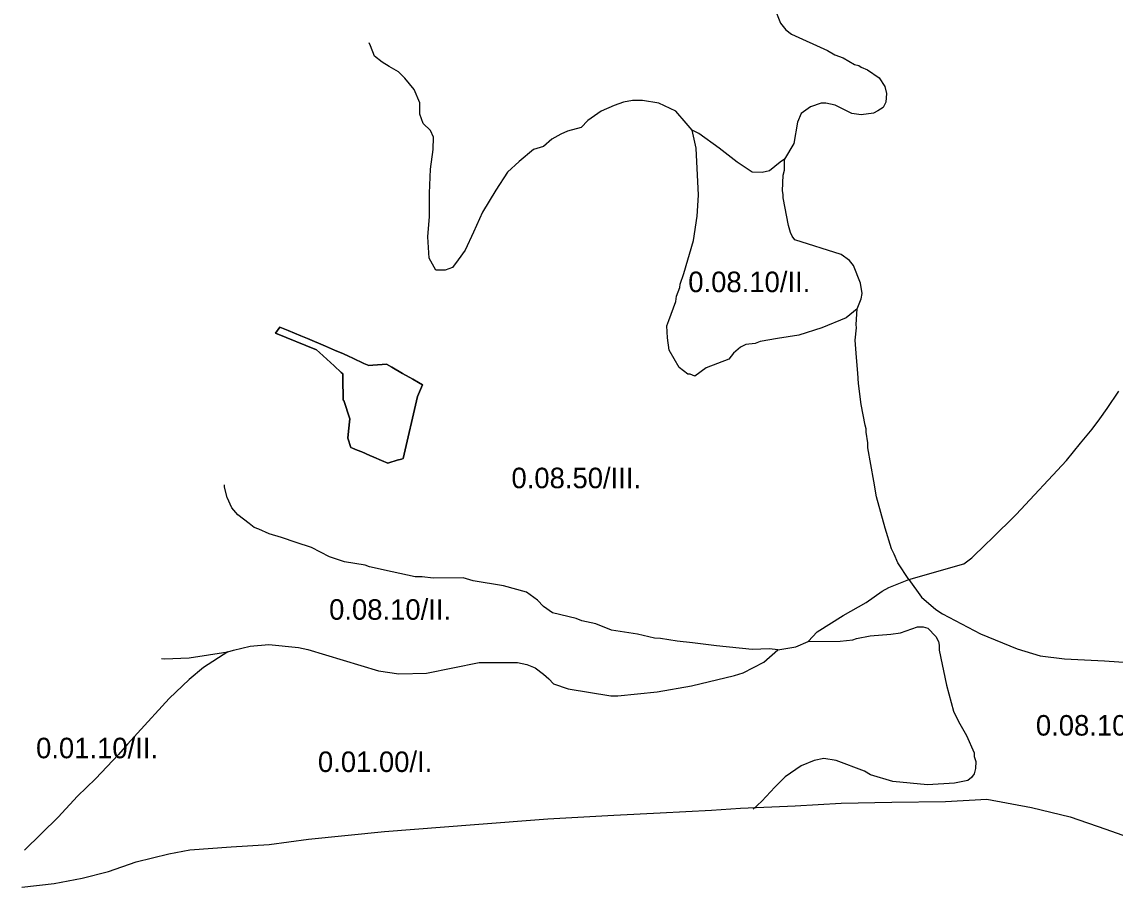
# Model space of a CAD drawing. Extents: x -555509 to -553014, y -1186753 to -1182560.
# Drawn here: x -555509 to -554443, y -1186742 to -1185899 of the extents above; entities that cross this region are included whole.
import ezdxf

# ---------------------------------------------------------------- set-up
doc = ezdxf.new("R2010")
doc.units = 0
for name, color, linetype in [('Level 29', 7, 'Continuous'), ('pěší_tr', 7, 'Continuous'), ('ZM2_KOO_legenda', 7, 'Continuous')]:
    doc.layers.add(name, color=color, linetype=linetype)

msp = doc.modelspace()

# ---------------------------------------------------------------- linework, layer by layer
at = {"layer": 'Level 29'}
for points in [[(-554775.2, -1185884.8), (-554768.9, -1185900.1), (-554763.8, -1185906.9), (-554758.3, -1185911.1), (-554723.1, -1185926.8), (-554715.9, -1185931), (-554707.8, -1185934), (-554696.8, -1185940.4), (-554692.6, -1185941.6), (-554690.1, -1185943.2), (-554684.1, -1185945.9), (-554672.6, -1185953.5), (-554667.1, -1185962), (-554665.4, -1185968.8), (-554666.3, -1185977.2), (-554668.8, -1185982.4), (-554673.9, -1185985.8), (-554678.2, -1185987.9), (-554690.1, -1185989.5), (-554699.4, -1185988.2), (-554715.5, -1185980.2), (-554724.8, -1185978.1), (-554729.1, -1185978.1), (-554739.6, -1185981.9), (-554748.6, -1185988.2), (-554752.4, -1185996.8), (-554755.8, -1186017.5), (-554765.1, -1186032.8)], [(-554854.9, -1186004.4), (-554860.9, -1185997.6), (-554871.1, -1185986.1), (-554887.6, -1185978.1), (-554903.3, -1185975.5), (-554913.1, -1185975.5), (-554921.9, -1185977.2), (-554931.2, -1185980.6), (-554943.6, -1185986.1), (-554956.7, -1185995), (-554963.1, -1186001.9), (-554976.6, -1186005.6), (-554983, -1186008.6), (-554991.9, -1186013.2), (-555000, -1186020.6), (-555009.8, -1186023.5), (-555023.8, -1186035), (-555035.2, -1186045.5), (-555046.6, -1186062.9), (-555059.3, -1186084.5), (-555068.2, -1186104), (-555076.2, -1186121.4), (-555083.1, -1186130.8), (-555088.6, -1186138.4), (-555095.8, -1186140.9), (-555105.1, -1186140.9), (-555111.4, -1186129.4), (-555112.7, -1186108.6), (-555111, -1186088.8), (-555111, -1186076), (-555111, -1186065.9), (-555110.2, -1186042.6), (-555107.6, -1186023.5), (-555107.2, -1186011.3), (-555110.2, -1186004.9), (-555117.4, -1185998.1), (-555120.4, -1185989.1), (-555120.4, -1185977.8), (-555126.2, -1185965), (-555135.2, -1185954), (-555141.5, -1185947.6), (-555150.4, -1185942.5), (-555157.2, -1185938.4), (-555164.8, -1185932.4), (-555168.6, -1185922.3), (-555170, -1185919.4)], [(-554694.2, -1186178.6), (-554704.9, -1186187.5), (-554728.6, -1186197.3), (-554751.1, -1186204.5), (-554771.9, -1186207.5), (-554788.8, -1186210.4), (-554793.5, -1186212.5), (-554802.8, -1186213.4), (-554807.9, -1186215.9), (-554814.7, -1186221.9), (-554819.4, -1186227.8), (-554841.4, -1186236.2), (-554852.4, -1186244.4), (-554857.1, -1186242.3), (-554859.2, -1186242.3), (-554867.7, -1186235.9), (-554877.4, -1186218.9), (-554879.1, -1186207), (-554879.6, -1186195.1), (-554877.9, -1186190.1), (-554871.1, -1186171.4), (-554870.2, -1186166.4), (-554867.2, -1186157.9), (-554866.8, -1186154.5), (-554863, -1186144.3), (-554853.7, -1186112), (-554850.3, -1186088.3), (-554849, -1186068), (-554851.1, -1186022.1), (-554854.9, -1186004.4)], [(-554765.1, -1186032.8), (-554769.3, -1186035.8), (-554779.5, -1186044.2), (-554786.7, -1186045.9), (-554796.4, -1186045.5), (-554811.3, -1186035.8), (-554828.7, -1186022.1), (-554848.6, -1186007.8), (-554854.9, -1186004.4)], [(-554694.2, -1186178.6), (-554690.4, -1186168.9), (-554689.2, -1186163.8), (-554690.9, -1186153.6), (-554697.7, -1186136.6), (-554701.5, -1186131.5), (-554709.6, -1186125.6), (-554754.9, -1186111.3), (-554757.4, -1186107.8), (-554759.1, -1186104.4), (-554761.2, -1186097.6), (-554766.4, -1186070.5), (-554766.4, -1186067.1), (-554766.8, -1186063.8), (-554766.4, -1186048.5), (-554765.1, -1186043.4), (-554765.1, -1186032.8)], [(-554643.8, -1186442.4), (-554654.4, -1186426.2), (-554658.2, -1186417.8), (-554660.8, -1186412.6), (-554666.7, -1186392.3), (-554675.2, -1186361.8), (-554677.8, -1186346.5), (-554683.7, -1186314.3), (-554683.7, -1186309.2), (-554685.4, -1186299), (-554685.4, -1186295.6), (-554686.2, -1186292.2), (-554690.4, -1186271.9), (-554693, -1186251.5), (-554693.4, -1186241.4), (-554694.7, -1186226.1), (-554696, -1186209.1), (-554694.7, -1186197.3), (-554695.1, -1186193.9), (-554694.2, -1186178.6)], [(-555261.3, -1186202.3), (-555256.9, -1186196.5), (-555248.8, -1186199.8), (-555242.7, -1186202.3), (-555236.7, -1186204.9), (-555230.2, -1186207.6), (-555212.6, -1186215.1), (-555203.7, -1186218.9), (-555194.9, -1186222.6), (-555190.1, -1186224.9), (-555186, -1186226.7), (-555175.1, -1186231.8), (-555170.2, -1186234), (-555166.5, -1186233.7), (-555157.3, -1186232.9), (-555153, -1186232.6), (-555147.8, -1186235.6), (-555137.4, -1186241.6), (-555127.5, -1186247.3), (-555121.9, -1186250.6), (-555117.9, -1186252.9), (-555122.8, -1186264), (-555136.8, -1186324.4), (-555138.4, -1186325.1), (-555142.5, -1186326.3), (-555150.7, -1186328.7), (-555151.7, -1186329), (-555157.9, -1186326.4), (-555165.4, -1186323.2), (-555169.3, -1186321.6), (-555177.2, -1186318.2), (-555181.7, -1186316.4), (-555186.3, -1186314.4), (-555187.7, -1186313.8), (-555190.8, -1186304.6), (-555190.1, -1186297.9), (-555188.9, -1186285.9), (-555194.7, -1186268.1), (-555195.2, -1186267.6), (-555195.6, -1186245.8), (-555195.7, -1186241.9), (-555197.2, -1186240.6), (-555204.2, -1186234.1), (-555218.3, -1186221.2), (-555221.4, -1186218.6), (-555261.3, -1186202.3)], [(-554643.8, -1186442.4), (-554590, -1186427.1), (-554582.4, -1186421.5), (-554568.8, -1186408), (-554563.2, -1186402.9), (-554539.1, -1186379.1), (-554489.9, -1186326.6), (-554476.4, -1186309.6), (-554464.9, -1186296), (-554457.7, -1186285.9), (-554450.5, -1186275.8), (-554439.1, -1186258.8)], [(-554771.4, -1186511), (-554779.5, -1186510.1), (-554796.4, -1186510.6), (-554831.2, -1186507.2), (-554854.6, -1186504.3), (-554869.8, -1186502.5), (-554885.9, -1186500), (-554891.9, -1186499.6), (-554908.4, -1186495.8), (-554933.8, -1186491.9), (-554949.1, -1186485.6), (-554962.6, -1186482.6), (-554968.2, -1186480.5), (-554991.1, -1186475), (-555000, -1186468.8), (-555005.9, -1186462.5), (-555016.5, -1186454.9), (-555039, -1186448.5), (-555068.6, -1186443.9), (-555078.4, -1186440.9), (-555107.6, -1186441.2), (-555118.2, -1186440), (-555125, -1186440), (-555147.4, -1186435), (-555169.5, -1186430.2), (-555173.8, -1186428.6), (-555194.1, -1186425.2), (-555203.8, -1186421.9), (-555208.5, -1186420.5), (-555226.2, -1186411.3), (-555241.1, -1186406.5), (-555255.5, -1186401.5), (-555267.4, -1186398.1), (-555277.6, -1186393.4), (-555282.2, -1186391.8), (-555286.9, -1186387.9), (-555297.9, -1186379.5), (-555303.8, -1186372.6), (-555308.5, -1186362.5), (-555311, -1186352.4), (-555311.1, -1186350.3)], [(-554741.8, -1186503), (-554733.2, -1186493.6), (-554707.8, -1186477.5), (-554685.4, -1186464.8), (-554669.7, -1186453.8), (-554663.3, -1186450.4), (-554643.8, -1186442.4)], [(-554643.8, -1186442.4), (-554631.5, -1186459.8), (-554617.6, -1186471.6), (-554610.8, -1186475.9), (-554573.9, -1186495.4), (-554538.2, -1186510.1), (-554515.8, -1186517), (-554492.1, -1186519.9), (-554453, -1186521.6), (-554411.1, -1186524.6), (-554390.2, -1186524.6), (-554377.6, -1186523.8), (-554366.9, -1186524.6)], [(-554741.8, -1186503), (-554710.8, -1186502.5), (-554698.5, -1186501.3), (-554694.7, -1186500), (-554681.6, -1186497.5), (-554661.2, -1186495.8), (-554651.9, -1186494.5), (-554635.3, -1186488.5), (-554629.8, -1186488.5), (-554625.2, -1186489.9), (-554617.6, -1186497.9), (-554615, -1186503), (-554614.1, -1186506.4), (-554614.1, -1186511.5), (-554606.9, -1186545.4), (-554600.1, -1186570.8), (-554595.5, -1186581), (-554587.4, -1186594.5), (-554580.2, -1186611.5), (-554580.2, -1186614.9), (-554578.5, -1186620), (-554578.9, -1186626.8), (-554580.2, -1186631.9), (-554582.8, -1186635.3), (-554586.2, -1186638.3), (-554599.3, -1186641.1), (-554625.6, -1186642.5), (-554659.5, -1186639.5), (-554681.1, -1186632.8), (-554687.1, -1186629.2), (-554714.6, -1186618.8), (-554726.5, -1186617), (-554736.2, -1186618.8), (-554748.9, -1186624.2), (-554764.2, -1186634.9), (-554774.4, -1186645), (-554787.1, -1186658.5), (-554795.6, -1186666.4)], [(-555307.6, -1186512.9), (-555302.1, -1186511.2), (-555286, -1186507.4), (-555267.8, -1186505.8), (-555239, -1186508.6), (-555229.7, -1186510.8), (-555161, -1186531.6), (-555141.1, -1186534.5), (-555114, -1186533.6), (-555062.7, -1186523.5), (-555025.4, -1186523.5), (-555016.1, -1186525.3), (-555008.1, -1186528.6), (-555000, -1186534.8), (-554994.9, -1186539.4), (-554990.2, -1186544.1), (-554975.8, -1186549.1), (-554934.2, -1186556), (-554927.4, -1186556), (-554889.3, -1186552.1), (-554855.8, -1186546.2), (-554813.8, -1186536), (-554805.4, -1186533.5), (-554785, -1186522.9), (-554771.4, -1186511)], [(-554771.4, -1186511), (-554754.1, -1186508), (-554741.8, -1186503)], [(-555307.6, -1186512.9), (-555331.4, -1186528.1), (-555345.4, -1186540), (-555364.8, -1186558.6), (-555395.8, -1186592.1), (-555405.5, -1186602.8), (-555414.4, -1186612.9), (-555436.9, -1186636.6), (-555454.2, -1186653.6), (-555473.3, -1186674), (-555506, -1186706.2)], [(-555372.3, -1186519.6), (-555369.5, -1186519.8), (-555345.4, -1186518.9), (-555307.6, -1186512.9)]]:
    msp.add_lwpolyline(points, dxfattribs=at)
at = {"layer": 'pěší_tr'}
msp.add_lwpolyline([(-555508.6, -1186742.3), (-555477.2, -1186738.9), (-555449.8, -1186733.4), (-555424, -1186726.9), (-555397, -1186717.7), (-555365.2, -1186709.8), (-555344.7, -1186706.1), (-555304.4, -1186703), (-555267.3, -1186700.7), (-555229, -1186695.6), (-555155.1, -1186688.2), (-555067.1, -1186681.2), (-554995.8, -1186675.7), (-554931.4, -1186672.3), (-554886.3, -1186670), (-554836.3, -1186667.3), (-554808, -1186665.4), (-554754.5, -1186663.2), (-554709.7, -1186660.4), (-554660.5, -1186659.4), (-554608, -1186658.9), (-554567.6, -1186656.7), (-554524.3, -1186664.8), (-554486.4, -1186673.7), (-554451.7, -1186685.7), (-554430.7, -1186693.2)], dxfattribs=at)
at = {"layer": 'ZM2_KOO_legenda'}
for p, q in [((-555256.9, -1186196.5), (-555261.3, -1186202.3)), ((-555248.8, -1186199.8), (-555256.9, -1186196.5)), ((-555261.3, -1186202.3), (-555221.4, -1186218.6)), ((-555242.7, -1186202.3), (-555248.8, -1186199.8)), ((-555236.7, -1186204.9), (-555242.7, -1186202.3)), ((-555230.2, -1186207.6), (-555236.7, -1186204.9)), ((-555212.6, -1186215.1), (-555230.2, -1186207.6)), ((-555221.4, -1186218.6), (-555218.3, -1186221.2)), ((-555203.7, -1186218.9), (-555212.6, -1186215.1)), ((-555194.9, -1186222.6), (-555203.7, -1186218.9)), ((-555218.3, -1186221.2), (-555204.2, -1186234.1)), ((-555190.1, -1186224.9), (-555194.9, -1186222.6)), ((-555186, -1186226.7), (-555190.1, -1186224.9)), ((-555175.1, -1186231.8), (-555186, -1186226.7)), ((-555204.2, -1186234.1), (-555197.2, -1186240.6)), ((-555197.2, -1186240.6), (-555195.7, -1186241.9)), ((-555170.2, -1186234), (-555175.1, -1186231.8)), ((-555166.5, -1186233.7), (-555170.2, -1186234)), ((-555157.3, -1186232.9), (-555166.5, -1186233.7)), ((-555153, -1186232.6), (-555157.3, -1186232.9)), ((-555147.8, -1186235.6), (-555153, -1186232.6)), ((-555137.4, -1186241.6), (-555147.8, -1186235.6)), ((-555195.7, -1186241.9), (-555195.6, -1186245.8)), ((-555195.6, -1186245.8), (-555195.2, -1186267.6)), ((-555127.5, -1186247.3), (-555137.4, -1186241.6)), ((-555121.9, -1186250.6), (-555127.5, -1186247.3)), ((-555117.9, -1186252.9), (-555121.9, -1186250.6)), ((-555122.8, -1186264), (-555117.9, -1186252.9)), ((-555195.2, -1186267.6), (-555194.7, -1186268.1)), ((-555194.7, -1186268.1), (-555188.9, -1186285.9)), ((-555136.8, -1186324.4), (-555122.8, -1186264)), ((-555188.9, -1186285.9), (-555190.1, -1186297.9)), ((-555190.1, -1186297.9), (-555190.8, -1186304.6)), ((-555190.8, -1186304.6), (-555187.7, -1186313.8)), ((-555187.7, -1186313.8), (-555186.3, -1186314.4)), ((-555186.3, -1186314.4), (-555181.7, -1186316.4)), ((-555181.7, -1186316.4), (-555177.2, -1186318.2)), ((-555177.2, -1186318.2), (-555169.3, -1186321.6)), ((-555169.3, -1186321.6), (-555165.4, -1186323.2)), ((-555165.4, -1186323.2), (-555157.9, -1186326.4)), ((-555142.5, -1186326.3), (-555138.4, -1186325.1)), ((-555138.4, -1186325.1), (-555136.8, -1186324.4)), ((-555157.9, -1186326.4), (-555151.7, -1186329)), ((-555151.7, -1186329), (-555150.7, -1186328.7)), ((-555150.7, -1186328.7), (-555142.5, -1186326.3))]:
    msp.add_line(p, q, dxfattribs=at)

# ---------------------------------------------------------------- texts
at = {"layer": 'Level 29'}
for s, p in [('0.08.10/II.', (-554858.8, -1186162.4)), ('0.08.50/III.', (-555031.2, -1186353.5)), ('0.08.10/II.', (-555209, -1186481.7)), ('0.08.10/II.', (-554519.9, -1186594.6)), ('0.01.10/II.', (-555494.7, -1186616.7)), ('0.01.00/I.', (-555219.9, -1186630.1))]:
    msp.add_text(s, height=20, dxfattribs=at).set_placement(p)

doc.saveas('drawing.dxf')
